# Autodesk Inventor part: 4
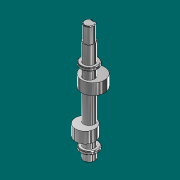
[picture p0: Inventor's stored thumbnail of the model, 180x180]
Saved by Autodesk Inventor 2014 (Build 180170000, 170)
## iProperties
Created: 2014-12
Part Number: 4
Material: 일반
Document SubType Name: Modeling
Designer: user
Density: 1 g/cm^3
Appearance: r
Author: user
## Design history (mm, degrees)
sketch "스케치22"
  geometry: C1 r 7.5 at (0, 0); 1 further point
  constraints: 1 centre point, 1 coincident
  dimensions: "d38" = 15 diameter of C1
extrude "돌출20" new body sketch "스케치22" distance "d39" = 24; taper "d40" = 0 deg
sketch "스케치23"
  geometry: C1 r 7.5 at (0, 0) reference; C2 r 8.5 at (0, 0)
  constraints: 1 centre point, 1 coincident
  dimensions: "d41" = 17 diameter of C2
extrude "돌출21" join sketch "스케치23" distance "d42" = 27; taper "d43" = 0 deg
sketch "스케치24"
  geometry: C1 r 8.5 at (0, 0) reference; C2 r 13 at (0, 0)
  constraints: 1 centre point, 1 coincident
  dimensions: "d44" = 26 diameter of C2
extrude "돌출22" join sketch "스케치24" distance "d45" = 5; taper "d46" = 0 deg
sketch "스케치25"
  geometry: C1 r 13 at (0, 0) reference; C2 r 8.5 at (0, 0)
  constraints: 1 centre point, 1 coincident
  dimensions: "d47" = 17 diameter of C2
extrude "돌출23" join sketch "스케치25" distance "d48" = 14.5; taper "d49" = 0 deg
sketch "스케치26"
  geometry: L1 (0, 0)-(0, 6); C1 r 8.5 at (0, 0) reference; C2 r 17.5 at (0, 6)
  constraints: 2 end point, 1 centre point, 1 coincident, 1 vertical
  dimensions: "d50" = 6 distance of L1.start L1.end; "d51" = 35 diameter of C2
extrude "돌출24" join sketch "스케치26" distance "d52" = 17; taper "d53" = 0 deg
sketch "스케치27"
  geometry: C1 r 8.5 at (0, -6); 1 further point
  constraints: 1 centre point, 1 coincident
  dimensions: "d54" = 17 diameter of C1
extrude "돌출25" join sketch "스케치27" distance "d55" = 43; taper "d56" = 0 deg
sketch "스케치28"
  geometry: L1 (0, 0)-(0, -6); C1 r 8.5 at (0, 0) reference; C2 r 15 at (0, -6)
  constraints: 2 end point, 1 centre point, 1 coincident, 1 vertical
  dimensions: "d57" = 6 distance of L1.start L1.end; "d58" = 30 diameter of C2
extrude "돌출26" join sketch "스케치28" distance "d59" = 17; taper "d60" = 0 deg
sketch "스케치29"
  geometry: C1 r 8.5 at (0, 6); 1 further point
  constraints: 1 centre point, 1 coincident
  dimensions: "d61" = 17 diameter of C1
extrude "돌출27" join sketch "스케치29" distance "d62" = 14.5; taper "d63" = 0 deg
sketch "스케치30"
  geometry: C1 r 8.5 at (0, 0) reference; C2 r 13 at (0, 0)
  constraints: 1 centre point, 1 coincident
  dimensions: "d64" = 26 diameter of C2
extrude "돌출28" join sketch "스케치30" distance "d65" = 5; taper "d66" = 0 deg
sketch "스케치31"
  geometry: C1 r 13 at (0, 0) reference; C2 r 8.5 at (0, 0)
  constraints: 1 centre point, 1 coincident
  dimensions: "d67" = 17 diameter of C2
extrude "돌출29" join sketch "스케치31" distance "d68" = 13; taper "d69" = 0 deg
chamfer "모따기1" distance "d70" = 1; stored, may be unused: second distance "d71" = 2, angle "d72" = 45 deg
chamfer "모따기2" distance "d73" = 1; stored, may be unused: second distance "d74" = 2, angle "d75" = 45 deg
chamfer "모따기3" distance "d76" = 1; stored, may be unused: second distance "d77" = 2, angle "d78" = 45 deg
sketch "스케치32"
  geometry: L1 (8.5, -70.5)-(23.5, -70.5) reference; L2 (23.5, -70.5)-(23.5, -87.5) reference; L3 (23.5, -87.5)-(8.5, -87.5) reference; L4 (8.5, -87.5)-(8.5, -130.5) reference; L5 (8.5, -130.5)-(9, -130.5) reference; L6 (9, -130.5)-(9, -147.5) reference; L7 (9, -147.5)-(8.5, -147.5) reference; L8 (8.5, -147.5)-(8.5, -162) reference; L9 (8.5, -162)-(12, -162) reference; L10 (12, -162)-(13, -163) reference; L11 (13, -163)-(13, -166) reference; L12 (13, -166)-(12, -167) reference; L13 (12, -167)-(8.5, -167) reference; L14 (8.5, -167)-(8.5, -179) reference; L15 (8.5, -179)-(7.5, -180) reference; L16 (7.5, -180)-(-7.5, -180) reference; L17 (-7.5, -180)-(-8.5, -179) reference; L18 (-8.5, -179)-(-8.5, -167) reference; L19 (-8.5, -167)-(-12, -167) reference; L20 (-12, -167)-(-13, -166) reference; L21 (-13, -166)-(-13, -163) reference; L22 (-13, -163)-(-12, -162) reference; L23 (-12, -162)-(-8.5, -162) reference; L24 (-8.5, -162)-(-8.5, -147.5) reference; L25 (-8.5, -147.5)-(-21, -147.5) reference; L26 (-21, -147.5)-(-21, -130.5) reference; L27 (-21, -130.5)-(-8.5, -130.5) reference; L28 (-8.5, -130.5)-(-8.5, -87.5) reference; L29 (-8.5, -87.5)-(-11.5, -87.5) reference; L30 (-11.5, -87.5)-(-11.5, -70.5) reference; L31 (-11.5, -70.5)-(-8.5, -70.5) reference; L32 (-8.5, -70.5)-(-8.5, -56) reference; L33 (-8.5, -56)-(-12, -56) reference; L34 (-12, -56)-(-13, -55) reference; L35 (-13, -55)-(-13, -52) reference; L36 (-13, -52)-(-12, -51) reference; L37 (-12, -51)-(-8.5, -51) reference; L38 (-8.5, -51)-(-8.5, -24) reference; L39 (-8.5, -24)-(-7.5, -24) reference; L40 (-7.5, -24)-(-7.5, -1) reference; L41 (-7.5, -1)-(-6.5, 0) reference; L42 (-6.5, 0)-(6.5, 0) reference; L43 (6.5, 0)-(7.5, -1) reference; L44 (7.5, -1)-(7.5, -24) reference; L45 (7.5, -24)-(8.5, -24) reference; L46 (8.5, -24)-(8.5, -51) reference; L47 (8.5, -51)-(12, -51) reference; L48 (12, -51)-(13, -52) reference; L49 (13, -52)-(13, -55) reference; L50 (13, -55)-(12, -56) reference; L51 (12, -56)-(8.5, -56) reference; L52 (8.5, -56)-(8.5, -70.5) reference; L53 (4.5, 2)-(12, 2); L54 (12, 2)-(12, -20); L55 (12, -20)-(4.5, -20); L56 (4.5, -20)-(4.5, 2); 1 further point
  constraints: 8 end point, 2 parallel, 1 horizontal, 1 perpendicular
  dimensions: "d79" = 3 distance between parallel lines of L56 L44; "d80" = 20 distance between parallel lines of L42 L55
extrude "돌출30" cut sketch "스케치32" stored distance "d81" = 5; taper "d82" = 0 deg
fillet "모깎기1" dims "d83" = 2.5
node "솔리드18"
node "절단 모서리 투영1"
